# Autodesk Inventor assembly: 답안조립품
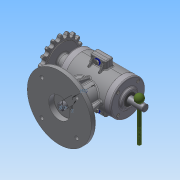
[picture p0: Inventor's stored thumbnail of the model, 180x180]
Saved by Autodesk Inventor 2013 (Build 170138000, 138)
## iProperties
Created: 2016-04
Part Number: 답안조립품
Document SubType Name: Assembly
Designer: Administrator
Author: Administrator
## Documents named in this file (19)
- C:\Users\Administrator\Desktop\360408V1020\답안조립품.iam
- C:\Users\Administrator\Desktop\360408V1020\너트 M4.ipt
- C:\Users\Administrator\Desktop\360408V1020\뒤커버.ipt
- C:\Users\Administrator\Desktop\360408V1020\레바.ipt
- C:\Users\Administrator\Desktop\360408V1020\멈춤나사 M3x8.ipt
- C:\Users\Administrator\Desktop\360408V1020\베어링 6201.ipt
- C:\Users\Administrator\Desktop\360408V1020\베어링 6202.ipt
- C:\Users\Administrator\Desktop\360408V1020\본체.ipt
- C:\Users\Administrator\Desktop\360408V1020\본체상부커버.ipt
- C:\Users\Administrator\Desktop\360408V1020\볼트 M3x0.5x8.ipt
- C:\Users\Administrator\Desktop\360408V1020\볼트 M4 x 16.ipt
- C:\Users\Administrator\Desktop\360408V1020\스프로킷.ipt
- C:\Users\Administrator\Desktop\360408V1020\슬라이드.ipt
- C:\Users\Administrator\Desktop\360408V1020\앞커버.ipt
- C:\Users\Administrator\Desktop\360408V1020\오일실 12 22 7.ipt
- C:\Users\Administrator\Desktop\360408V1020\와셔 ST 4-100.ipt
- C:\Users\Administrator\Desktop\360408V1020\키 4 x 4 x 18.ipt
- C:\Users\Administrator\Desktop\360408V1020\편심축.ipt
- C:\Users\Administrator\Desktop\360408V1020\스프링.ipt
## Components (6 placed, 3 different names)
1. ISO 4032 M4:1
2. ISO 4762 M4 x 16:1
3. ISO 7091 ST 4 - 100 HV:1
4. ISO 4762 M4 x 16:2
5. ISO 4032 M4:2
6. ISO 7091 ST 4 - 100 HV:2
